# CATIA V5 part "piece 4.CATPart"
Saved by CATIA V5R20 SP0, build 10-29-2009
Part number: piece 4
Bounding box of the stored display mesh (mm): x -93.525 to 266.475, y -15 to 0, z 0 to 2
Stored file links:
  G:\Khaled_CFAO_2011\SIL\SIL_GR1\blaboucarri\Khaled\CAD_CATIA\piece 4.CATPart
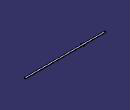
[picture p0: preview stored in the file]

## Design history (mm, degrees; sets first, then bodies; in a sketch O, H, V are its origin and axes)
Parameters
  `longueur piece 4` = 360 mm
  `largeur piece 4` = 7 mm
  `epaisseur piece 4` = 2 mm
  `distance butée` = 250 mm
  LENGTH = 0 mm
  `dimension butée` = 2 mm
  `rayon trou` = 1.5 mm
  `distance trou bord` = 1 mm
Body1 (main body)
  Point1: stored without definition
  Point2: stored without definition
  Sketch1 on xy-plane, origin (0, 0, 0), H (1, 0, 0), V (0, 1, 0)
    point P1 (-93.5252, -4)
    line L1 (-91.7964, -4) -> (7.3895, -4)
    point P3 (148.4748, -4)
    line L2 (148.4748, -4) -> (263.299, -4)
    line L3 (266.4748, -7.1758) -> (266.4748, -7.3668)
    line L4 (262.8416, -11) -> (148.4748, -11)
    point P5 (146.4748, -11)
    line L5 (146.4748, -11) -> (11.3895, -11)
    point P6 (-93.5252, -11)
    line L6 (-93.5252, -8.997) -> (-93.5252, -5.7287)
    arc A1 centre (-91.7964, -5.7287) radius 1.7287 from (-91.7964, -4) to (-93.5252, -5.7287) ccw
    arc A2 centre (-91.5221, -8.997) radius 2.003 from (-91.5221, -11) to (-93.5252, -8.997) cw
    arc A3 centre (263.299, -7.1758) radius 3.1758 from (266.4748, -7.1758) to (263.299, -4) ccw
    arc A4 centre (262.8416, -7.3668) radius 3.6332 from (262.8416, -11) to (266.4748, -7.3668) ccw
    circle A5 centre (-91.0252, -7.5) radius 1.5
    point P19 (-91.0252, -7.5)
    circle A6 centre (263.9748, -7.5) radius 1.5
    point P20 (263.9748, -7.5)
    point P21 (263.1713, -6.2334)
    line L7 (7.3895, -4) -> (7.3895, 0)
    point P23 (7.3895, 0)
    line L8 (7.3895, 0) -> (11.3895, 0)
    line L9 (11.3895, 0) -> (11.3895, -4)
    point P25 (11.3895, -4)
    line L10 (7.3895, -11) -> (7.3895, -15)
    point P26 (7.3895, -11)
    line L11 (7.3895, -15) -> (11.3895, -15)
    point P28 (11.3895, -15)
    line L12 (11.3895, -15) -> (11.3895, -11)
    line L13 (11.3895, -4) -> (146.4748, -4)
    line L14 (7.3895, -11) -> (-91.5221, -11)
    line L15 (146.4748, -4) -> (148.4748, -4)
    line L16 (148.4748, -11) -> (146.4748, -11)
    reference projected point E1 (261.3895, -7.9295) from Point2
    distance L3 L6 = 360 {= `longueur piece 4`}
    distance P6 P1 = 7 {= `largeur piece 4`}
    radius A1 = 1.7287
    radius A2 = 2.003
    radius A3 = 3.1758
    radius A4 = 3.6332
    radius A5 = 1.5 {= `rayon trou`}
    distance P19 L6 = 2.5 {= `rayon trou` +`distance trou bord`}
    radius A6 = 1.5 {= `rayon trou`}
    distance P20 L3 = 2.5 {= `rayon trou` +`distance trou bord`}
    distance P19 L1 = 3.5 {= `largeur piece 4` /2}
    distance P20 L2 = 3.5 {= `largeur piece 4` /2}
    length L9 = 4
    length L8 = 4
    length L12 = 4
    distance L9 E1 = 250 {= `distance butée`}
    horizontal: L1 H, L2 H, L4 H, L5 H, L8 H, L11 H, L13 H, L14 H, L15 H, L16 H
    coincidence: P3 L1, P5 L4, L1 P1, L6 P1, L5 P6, L6 P6, A6 P21, P23 H, P25 L1, P26 L7, P26 L5, P28 L9, L1 L13, L5 L14
    vertical: L3 V, L6 V, L7 V, L9 V, L10 V, L12 V
    tangency: A1 L1, A1 L6, A2 L5, A2 L6, A3 L3, A3 L2, A4 L4, A4 L3
  Pad1: profile Sketch1, direction (0, 0, 1), length 2 {= `epaisseur piece 4`}
  Point3: type Center, Curve edge [face of Pad1 from Sketch1.A6 | start face of Pad1]
  Line1: type PtDir, RefPoint Point3, Direction start face of Pad1, Start 0, End 20
  Plane1: type Normal, Curve Line1, RefPoint Point3
  Plane2: type Offset, RefPlane Plane1, Offset 1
